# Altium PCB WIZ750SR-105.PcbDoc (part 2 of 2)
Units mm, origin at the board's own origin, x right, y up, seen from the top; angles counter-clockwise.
Board outline 62 x 40 mm, 4 copper layers (Top Layer, Signal Layer 1, Internal Plane 1, Bottom Layer), stack 0.844 mm thick; 87 components, 85 nets, 410 pads, 285 vias.
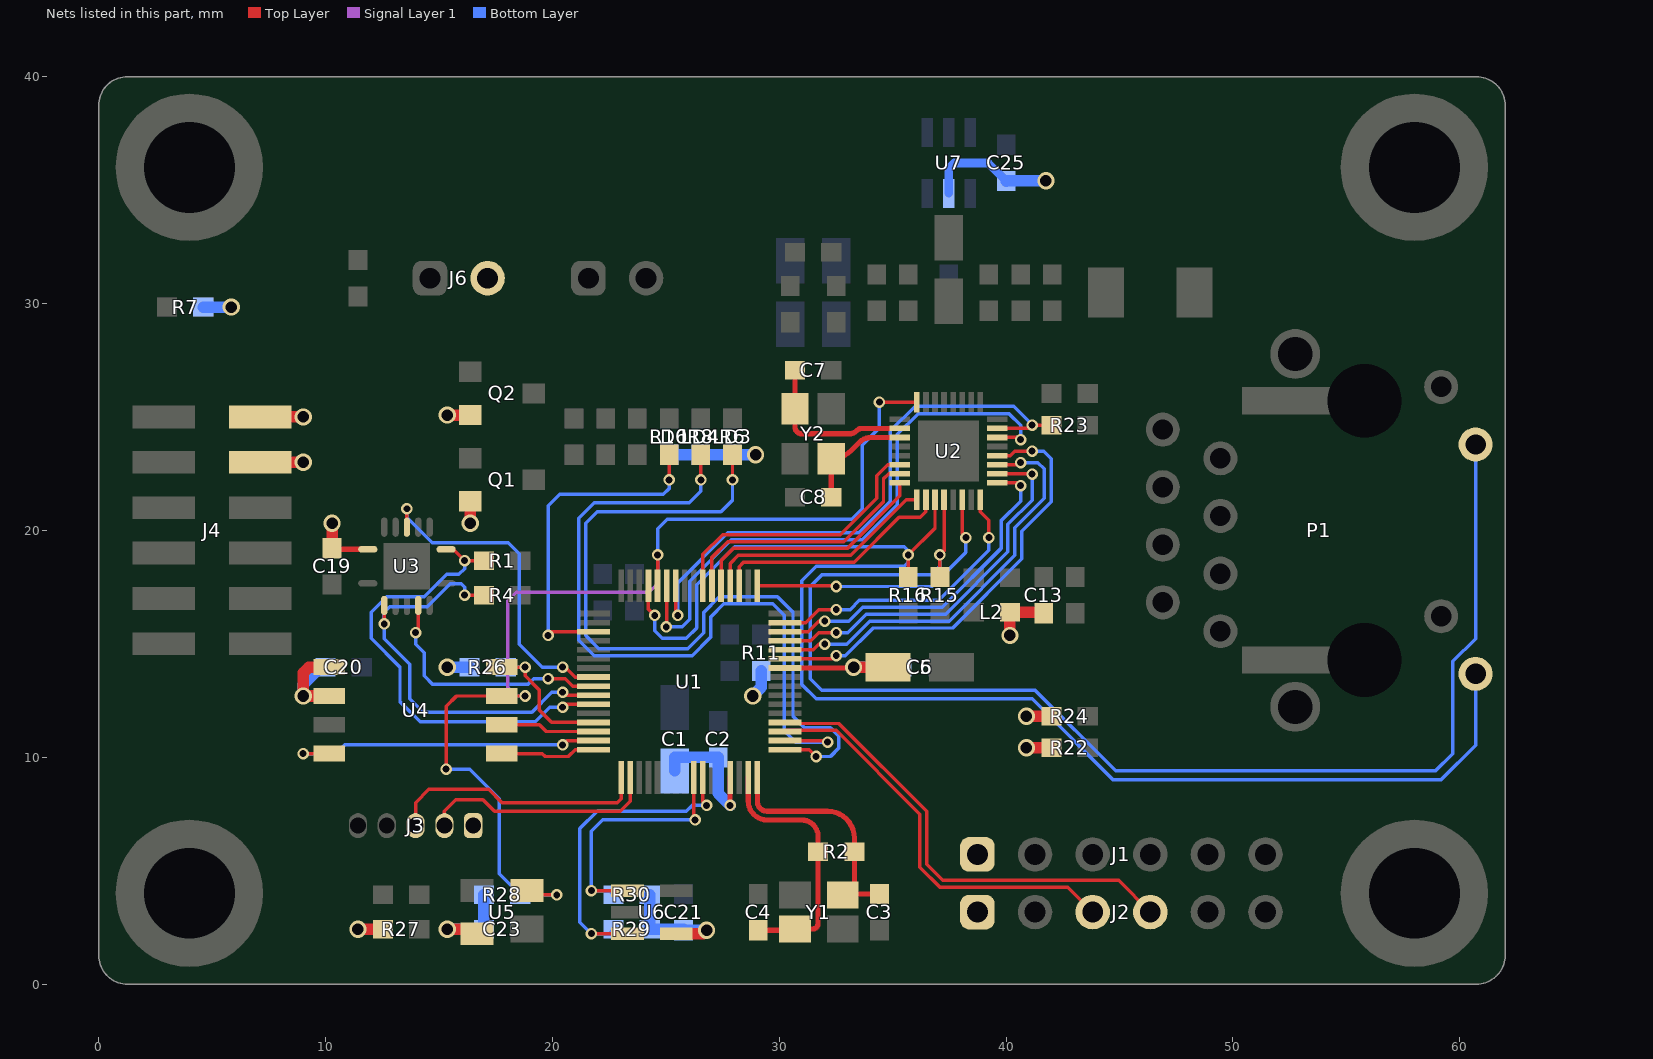
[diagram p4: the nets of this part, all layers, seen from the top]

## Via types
v1: diameter 0.508, hole 0.305, Top Layer to Bottom Layer, tented both sides, 164 vias
v2: diameter 0.762, hole 0.508, Top Layer to Bottom Layer, tented both sides, 119 vias
v3: diameter 0.508, hole 0.305, Top Layer to Bottom Layer, 1 vias
v4: diameter 0.508, hole 0.305, Top Layer to Bottom Layer, tented top, 1 vias

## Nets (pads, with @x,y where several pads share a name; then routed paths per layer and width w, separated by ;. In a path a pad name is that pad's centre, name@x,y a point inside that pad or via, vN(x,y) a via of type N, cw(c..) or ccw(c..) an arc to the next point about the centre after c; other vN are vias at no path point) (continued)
PB_07: U1.17 U2.14 | length 12.8
  Top Layer w0.152: U1.17@29.035,18.138 U1.17@29.035,17.56 32.478,17.56 v1(32.512,17.526) ; U2.14@38.065,21.345 38.065,19.847 v1(38.227,19.685)
  Bottom Layer w0.152: v1(32.512,17.526) 36.728,17.526 38.227,19.025 v1(38.227,19.685)
PB_09: U1.19 U2.10 | length 10.6
  Top Layer w0.152: U1.19@28.235,17.56 28.235,18.405 28.423,18.593 33.299,18.593 35.281,20.574 36.211,20.574 36.465,20.828 U2.10@36.465,21.345
PB_10: U1.20 U2.9 | length 10.4
  Top Layer w0.152: U1.20@27.835,17.56 27.835,18.539 28.194,18.898 33.147,18.898 35.594,21.345 U2.9@36.065,21.345
PB_11: U1.21 U2.8 | length 10.7
  Top Layer w0.152: U1.21@27.435,17.56 27.435,18.672 27.965,19.202 32.995,19.202 35.315,21.523 U2.8@35.315,22.095
PB_12: U1.22 U2.7 | length 11.6
  Top Layer w0.152: U1.22@27.035,17.56 27.035,18.805 27.737,19.507 32.842,19.507 34.595,21.26 34.595,22.27 34.82,22.495 U2.7@35.315,22.495
PB_13: U1.23 U2.6 | length 12.3
  Top Layer w0.152: U1.23@26.635,17.56 26.635,18.939 27.508,19.812 32.69,19.812 34.29,21.412 34.29,22.403 34.782,22.895 U2.6@35.315,22.895
PB_14: R23.1 U1.26 U2.23 | length 26.2
  Top Layer w0.152: U1.26@25.435,17.56 25.435,16.348 v1(25.527,16.256) ; U2.23@39.615,24.495 41.005,24.495 v1(41.148,24.638) R23.1@41.999,24.638
  Bottom Layer w0.152: v1(25.527,16.256) 25.527,17.678 27.737,19.888 33.503,19.888 34.9,21.285 34.9,24.384 35.992,25.476 40.331,25.476 41.148,24.659 v1(41.148,24.638)
PB_15: U1.27 U2.22 | length 26
  Top Layer w0.152: v1(25.019,15.748) 25.035,15.764 U1.27@25.035,17.56 ; U2.22@39.615,24.095 40.548,24.095 v1(40.64,24.003)
  Bottom Layer w0.152: v1(25.019,15.748) 25.73,15.748 26.06,16.078 26.06,17.755 27.889,19.583 33.655,19.583 35.204,21.133 35.204,24.232 36.119,25.146 40.129,25.146 40.64,24.635 v1(40.64,24.003)
PD_00: U1.11 U2.20 | length 19.8
  Top Layer w0.152: U1.11@30.26,14.335 32.369,14.335 v1(32.512,14.478) ; U2.20@39.615,23.295 40.186,23.295 40.386,23.495 v1(41.148,23.495)
  Bottom Layer w0.152: v1(32.512,14.478) 32.918,14.478 34.138,15.697 37.643,15.697 40.691,18.745 40.691,19.964 41.986,21.26 41.986,23.165 41.656,23.495 v1(41.148,23.495)
PD_01: U1.12 U2.19 | length 18.4
  Top Layer w0.152: U1.12@30.26,14.735 31.499,14.735 31.75,14.986 v1(32.004,14.986) ; U2.19@39.615,22.895 40.548,22.895 v1(40.64,22.987)
  Bottom Layer w0.152: v1(32.004,14.986) 32.969,14.986 33.985,16.002 37.49,16.002 40.386,18.898 40.386,20.117 41.681,21.412 41.681,22.708 41.402,22.987 v1(40.64,22.987)
PD_02: U1.13 U2.18 | length 16.9
  Top Layer w0.152: U1.13@30.26,15.135 31.391,15.135 31.75,15.494 v1(32.512,15.494) ; U2.18@39.615,22.495 41.132,22.495 v1(41.148,22.479)
  Bottom Layer w0.152: v1(32.512,15.494) 33.02,15.494 33.833,16.307 37.338,16.307 40.081,19.05 40.081,20.269 41.148,21.336 v1(41.148,22.479)
PD_03: U1.14 U2.17 | length 15.2
  Top Layer w0.152: U1.14@30.26,15.535 31.283,15.535 31.75,16.002 v1(32.004,16.002) ; U2.17@39.615,22.095 40.516,22.095 v1(40.64,21.971)
  Bottom Layer w0.152: v1(32.004,16.002) 33.071,16.002 33.68,16.612 37.186,16.612 39.776,19.202 39.776,20.422 40.64,21.285 v1(40.64,21.971)
PD_04: U1.15 U2.16 | length 12.7
  Top Layer w0.152: U1.15@30.26,15.935 31.175,15.935 31.75,16.51 v1(32.512,16.51) ; U2.16@38.865,21.345 38.865,20.825 39.243,20.447 v1(39.243,19.685)
  Bottom Layer w0.152: v1(32.512,16.51) 33.122,16.51 33.528,16.916 37.033,16.916 39.243,19.126 v1(39.243,19.685)
PHY_AD0: P1.L4 R16.2 U1.29 U2.11 | length 65.5
  Top Layer w0.152: U1.29@24.235,17.56 24.235,16.532 v1(24.511,16.256) ; R16.2@35.687,17.945 v1(35.687,18.923) 36.865,20.101 U2.11@36.865,21.345
  Bottom Layer w0.152: v1(24.511,16.256) 24.511,15.57 24.841,15.24 25.908,15.24 26.365,15.697 26.365,17.602 28.042,19.279 35.509,19.279 35.687,19.101 v1(35.687,18.923) 35.687,18.59 35.512,18.415 31.623,18.415 30.988,17.78 30.988,13.208 31.623,12.573 41.148,12.573 44.704,9.017 59.182,9.017 60.695,10.53 P1.L4@60.695,13.675
PHY_AD3: P1.L2 R15.2 U2.12 | length 58.5
  Top Layer w0.152: R15.2@37.084,17.945 v1(37.084,18.923) 37.265,19.104 U2.12@37.265,21.345
  Bottom Layer w0.152: v1(37.084,18.923) 37.084,18.415 36.703,18.034 31.877,18.034 31.369,17.526 31.369,13.462 31.877,12.954 41.275,12.954 44.831,9.398 58.928,9.398 59.69,10.16 59.69,14.224 60.695,15.229 P1.L2@60.695,23.785
RESETN: R28.1 U1.28 U2.32 U4.3 U5.2 | length 48.4
  Top Layer w0.152: v3(15.316,9.474) 15.316,12.243 15.773,12.7 U4.3@17.77,12.7 v1(18.796,12.7) ; U5.2@18.88,4.125 19.068,3.937 v1(20.193,3.937) ; U1.28@24.635,17.56 24.635,18.92 v1(24.638,18.923) ; v1(34.417,25.654) 34.417,25.645 U2.32@36.065,25.645
  Signal Layer 1 w0.152: v1(18.796,12.7) 18.415,12.7 18.034,13.081 18.034,16.891 18.415,17.272 24.257,17.272 24.638,17.653 v1(24.638,18.923)
  Bottom Layer w0.152: v3(15.316,9.474) 16.358,9.474 17.653,8.179 17.653,4.864 R28.1@18.58,3.937 v1(20.193,3.937) ; v1(24.638,18.923) 24.638,20.066 25.07,20.498 33.198,20.498 33.655,20.955 33.655,23.749 34.417,24.511 v1(34.417,25.654)
SCL1: R30.1 U1.57 U6.1 | length 11.9
  Top Layer w0.152: v1(21.717,4.125) U6.1@23.309,4.125 ; U1.57@26.235,9.11 26.235,7.293 v1(26.289,7.239)
  Bottom Layer w0.152: R30.1@22.695,3.937 22.507,4.125 v1(21.717,4.125) 21.717,6.731 22.225,7.239 v1(26.289,7.239)
SDA1: R29.1 U1.58 U6.3 | length 14.8
  Top Layer w0.152: v1(21.717,2.225) U6.3@23.309,2.225 ; U1.58@26.635,9.11 26.635,8.036 v1(26.797,7.874)
  Bottom Layer w0.152: R29.1@22.695,2.413 22.507,2.225 v1(21.717,2.225) 21.209,2.733 21.209,6.858 21.971,7.62 25.908,7.62 26.162,7.874 v1(26.797,7.874)
SPI_MISO1: U1.47 U4.8 | length 14.2
  Top Layer w0.152: v1(9.017,10.16) U4.8@10.17,10.16 ; v1(20.447,10.541) 20.641,10.735 U1.47@21.81,10.735
  Bottom Layer w0.152: v1(9.017,10.16) 10.465,10.16 10.846,10.541 v1(20.447,10.541)
SPI_MOSI1: U1.48 U4.1 | length 4.2
  Top Layer w0.152: U4.1@17.77,10.16 19.558,10.16 19.685,10.033 20.701,10.033 21.003,10.335 U1.48@21.81,10.335
SPI_SCLK1: U1.46 U4.2 | length 4.2
  Top Layer w0.152: U4.2@17.77,11.43 19.431,11.43 19.726,11.135 U1.46@21.81,11.135
SPI_SSEL1: R26.1 U1.45 U4.4 | length 6.6
  Top Layer w0.152: U4.4@17.77,13.97 v1(18.796,13.97) 18.796,13.589 19.431,12.954 19.431,12.065 19.961,11.535 U1.45@21.81,11.535
  Bottom Layer w0.152: R26.1@17.945,13.97 v1(18.796,13.97)
STATUS: LD6.2 U1.35 | length 14.9
  Top Layer w0.152: v1(19.812,15.367) 19.98,15.535 U1.35@21.81,15.535 ; v1(25.146,22.225) LD6.2@25.146,23.33
  Bottom Layer w0.152: v1(19.812,15.367) 19.812,21.082 20.32,21.59 24.892,21.59 25.146,21.844 v1(25.146,22.225)
STATUS_LED0: LD3.2 U1.1 | length 35.1
  Top Layer w0.152: v1(27.94,22.225) LD3.2@27.94,23.33 ; U1.1@30.26,10.335 31.321,10.335 v1(31.623,10.033)
  Bottom Layer w0.152: v1(27.94,22.225) 27.94,21.336 27.432,20.828 21.971,20.828 21.463,20.32 21.463,15.367 22.047,14.783 25.959,14.783 26.669,15.493 26.669,16.382 27.356,17.069 29.921,17.069 30.607,16.383 30.607,11.811 31.115,11.303 32.258,11.303 32.614,10.947 32.614,10.389 32.258,10.033 v1(31.623,10.033)
STATUS_LED1: LD4.2 U1.2 | length 33
  Top Layer w0.152: v1(26.543,22.225) LD4.2@26.543,23.33 ; U1.2@30.26,10.735 32.064,10.735 v1(32.131,10.668)
  Bottom Layer w0.152: v1(26.543,22.225) 26.543,21.717 26.035,21.209 21.844,21.209 21.161,20.526 21.161,15.161 21.844,14.478 26.162,14.478 26.971,15.287 26.971,16.176 27.559,16.764 29.718,16.764 30.226,16.256 30.226,11.176 30.734,10.668 v1(32.131,10.668)
SWCLK: J3.3 U1.49 | length 11.6
  Top Layer w0.152: J3.3@13.97,6.985 13.97,8.001 14.554,8.585 15.589,8.585 17.196,8.585 17.78,8.001 22.86,8.001 23.035,8.176 U1.49@23.035,9.11
SWDIO: J3.2 U1.50 | length 10.5
  Top Layer w0.152: J3.2@15.24,6.985 15.24,7.62 15.748,8.128 16.942,8.128 17.45,7.62 22.987,7.62 23.435,8.068 U1.50@23.435,9.11
U_CTS0: U1.40 U3.11 | length 14.7
  Top Layer w0.152: U3.11@13.589,20.14 v1(13.589,20.955) ; v1(20.447,13.97) 20.574,13.97 21.009,13.535 U1.40@21.81,13.535
  Bottom Layer w0.152: v1(13.589,20.955) 13.589,20.574 14.707,19.456 18.059,19.456 18.542,18.974 18.542,14.986 19.558,13.97 v1(20.447,13.97)
U_RTS0: U1.41 U3.5 | length 11.2
  Top Layer w0.152: v1(13.97,15.494) 14.089,15.613 U3.5@14.089,16.69 ; v1(19.812,13.462) 20.574,13.462 20.901,13.135 U1.41@21.81,13.135
  Bottom Layer w0.152: v1(13.97,15.494) 13.97,14.986 14.351,14.605 14.351,13.589 14.732,13.208 18.923,13.208 19.177,13.462 v1(19.812,13.462)
U_RXD0: R1.2 U1.43 U3.8 | length 20.8
  Top Layer w0.152: U3.8@15.314,19.165 15.633,19.165 v1(16.129,18.669) R1.2@16.98,18.669 ; v1(20.447,12.205) 20.577,12.335 U1.43@21.81,12.335
  Bottom Layer w0.152: v1(16.129,18.669) 16.129,18.313 15.875,18.059 15.342,18.059 14.352,17.069 12.701,17.069 12.014,16.382 12.014,15.24 13.284,13.97 13.284,12.447 13.373,12.357 14.174,11.557 19.24,11.557 19.888,12.205 v1(20.447,12.205)
U_RXD2: J2.4 U1.4 | length 20.9
  Top Layer w0.152: U1.4@30.26,11.535 30.308,11.487 32.632,11.487 36.5,7.619 36.5,5.283 37.211,4.572 44.958,4.572 J2.4@46.355,3.175
U_TXD0: R4.2 U1.42 U3.2 | length 19.2
  Top Layer w0.152: v1(12.589,15.875) U3.2@12.589,16.69 ; v1(16.129,17.145) R4.2@16.98,17.145 ; v1(20.447,12.865) 20.577,12.735 U1.42@21.81,12.735
  Bottom Layer w0.152: v1(16.129,17.145) 16.129,17.501 15.977,17.653 15.494,17.653 14.478,16.637 12.827,16.637 12.573,16.383 12.573,15.891 v1(12.589,15.875) 12.589,15.224 13.716,14.097 13.716,12.573 14.3,11.989 19.101,11.989 19.977,12.865 v1(20.447,12.865)
U_TXD2: J2.3 U1.3 | length 18.3
  Top Layer w0.152: U1.3@30.26,11.135 30.308,11.183 32.505,11.183 36.195,7.493 36.195,5.157 37.085,4.267 42.723,4.267 J2.3@43.815,3.175
VCC_3.3V: C1.1 C2.2 C5.1 C6.2 C13.2 C19.1 C20.1 C21.2 C23.2 C25.1 J1.1 J2.1 J3.1 J4.2 J4.4 J6.2 L2.1 Q1.2 Q2.2 R6.2 R7.1 R8.2 R10.2 R11.2 R22.1 R24.1 R26.2 R27.2 R28.2 R29.2 R30.2 U1.10 U1.61 U3.14 U4.5 U4.6 U5.4 U6.4 U7.5 | length 55.2
  Top Layer w0.229: v1(27.835,7.874) U1.61@27.835,9.11 ; U1.10@30.26,13.935 33.239,13.935 v2(33.274,13.97)
  Top Layer w0.254: C19.1@10.287,19.215 C19.1@10.337,19.165 ; C19.1@10.464,19.165 U3.14@11.864,19.165
  Top Layer w0.508: J4.4@7.13,23 v2(9.017,23) ; J4.2@7.13,25 v2(9.017,25) ; U4.6@10.17,12.7 v2(9.017,12.7) 9.017,13.716 9.271,13.97 U4.5@10.17,13.97 ; C19.1@10.287,19.215 v2(10.287,20.32) ; v2(11.43,2.413) R27.2@12.535,2.413 ; v2(15.367,2.413) 16.492,2.413 U5.4@16.68,2.225 ; v2(15.367,25.085) Q2.2@16.38,25.085 ; Q1.2@16.38,21.275 16.383,21.272 v2(16.383,20.32) ; U6.4@25.459,2.225 26.647,2.225 v2(26.797,2.375) ; v2(33.274,13.97) C5.1@34.795,13.97 ; v2(40.17,15.367) L2.1@40.17,16.383 41.618,16.383 C13.2@41.656,16.345 ; v2(40.894,10.414) R22.1@41.999,10.414 ; v2(40.894,11.811) R24.1@41.999,11.811
  Bottom Layer w0.381: U7.5@37.465,34.855 37.465,35.941 37.719,36.195 39.205,36.195 C25.1@40.005,35.395
  Bottom Layer w0.508: R7.1@4.61,29.845 v2(5.842,29.845) ; v2(9.017,12.7) 9.017,13.208 9.779,13.97 C20.1@9.995,13.97 ; v2(15.367,2.413) C23.2@16.98,2.413 R28.2@16.98,3.937 ; v2(15.367,13.97) R26.2@16.345,13.97 ; R30.2@24.295,3.937 R29.2@24.295,2.413 25.781,2.413 C21.2@25.781,2.375 v2(26.797,2.375) ; R10.2@25.146,23.33 R8.2@26.543,23.33 R6.2@27.94,23.33 v2(28.956,23.33) ; C1.1@25.4,9.395 25.4,9.995 C2.2@27.305,9.995 27.305,8.404 v1(27.835,7.874) ; v2(28.829,12.7) 29.21,13.081 R11.2@29.21,13.805 ; v2(33.274,13.97) C6.2@35.395,13.97 ; C25.1@40.005,35.395 40.018,35.408 v2(41.758,35.408)
XIN: C4.2 R2.2 U1.63 Y1.3 | length 11.6
  Top Layer w0.229: U1.63@28.635,9.11 28.635,8.063 ccw(c29.464,8.063) 29.464,7.234 30.988,7.234 cw(c30.988,6.51) 31.712,6.51 R2.2@31.712,5.842 31.712,2.667 cw(c31.47,2.667) 31.47,2.425 Y1.3@30.7,2.425 cw(c30.65,2.425) 30.65,2.375 C4.2@29.083,2.375
XOUT: C3.2 R2.1 U1.64 Y1.1 | length 10.6
  Top Layer w0.229: U1.64@29.035,9.11 29.035,8.049 ccw(c29.464,8.049) 29.464,7.62 32.131,7.62 cw(c32.131,6.439) 33.312,6.439 R2.1@33.312,5.842 33.312,4.437 cw(c32.85,4.437) 32.85,3.975 C3.2@34.417,3.975
XTAL1: C7.2 U2.2 Y2.1 | length 7.4
  Top Layer w0.229: C7.2@30.696,27.051 Y2.1@30.696,25.357 30.696,24.549 ccw(c30.988,24.549) 30.988,24.257 33.094,24.257 ccw(c33.094,24.691) 33.401,24.384 cw(c33.669,24.116) 33.669,24.495 U2.2@35.315,24.495
XTAL2: C8.2 U2.3 Y2.3 | length 5
  Top Layer w0.229: C8.2@32.296,21.463 Y2.3@32.296,23.157 ccw(c32.296,24.395) 33.172,23.52 33.528,23.876 cw(c34.057,23.347) 34.057,24.095 U2.3@35.315,24.095
pads on no net: J4.10 M1.1 M2.1 M4.1 P1. P1.R4 P1.R5 P1.R6 U1.30 U1.31 U1.33 U1.38 U1.44 U1.51 U1.52 U1.53 U1.54 U1.55 U1.56 U1.59 U1.60 U2.1 U2.21
copper on no net:
  other v2: 4,1.4 58,1.4 2.162,2.162 5.838,2.162 56.162,2.162 59.838,2.162 1.4,4 6.6,4 55.4,4 60.6,4 2.162,5.838 5.838,5.838 56.162,5.838 59.838,5.838 4,6.6 58,6.6 4,33.4 2.162,34.162 5.838,34.162 1.4,36 6.6,36 2.162,37.838 5.838,37.838 4,38.6

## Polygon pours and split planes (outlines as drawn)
CH_GND on Top Layer "Top Layer-NET" (solid, remove dead copper, pour order 14): 61.341,39.116 61.341,28.321 61.087,28.067 54.483,28.067 53.34,26.924 52.197,26.924 51.054,28.067 47.752,28.067 47.498,28.321 47.498,39.116 47.752,39.37 61.087,39.37
GND on Top Layer "Top Layer-GND" (solid, remove dead copper, pour order 18): 42.545,28.956 42.545,26.797 42.291,26.543 42.037,26.543 33.909,26.543 33.655,26.797 33.655,27.178 33.655,28.956
GND on Top Layer "Top Layer-GND" (solid, remove dead copper, pour order 20): 45.212,36.195 45.212,9.144 45.466,8.89 45.72,8.89 52.832,8.89 53.086,8.636 53.086,8.382 53.086,0.889 52.832,0.635 52.451,0.635 9.144,0.635 8.89,0.889 8.89,1.016 8.89,8.636 8.636,8.89 7.493,8.89 0.889,8.89 0.635,9.144 0.635,9.271 0.635,30.861 0.889,31.115 1.27,31.115 8.636,31.115 8.89,31.369 8.89,31.496 8.89,39.116 9.144,39.37 9.398,39.37 44.958,39.37 45.212,39.116
GND on Bottom Layer "Top Layer-GND" (solid, remove dead copper, pour order 8): 45.212,36.195 45.212,9.144 45.466,8.89 45.72,8.89 52.832,8.89 53.086,8.636 53.086,8.382 53.086,0.889 52.832,0.635 52.451,0.635 9.144,0.635 8.89,0.889 8.89,1.016 8.89,8.636 8.636,8.89 7.493,8.89 0.889,8.89 0.635,9.144 0.635,9.271 0.635,30.861 0.889,31.115 1.27,31.115 8.636,31.115 8.89,31.369 8.89,31.496 8.89,39.116 9.144,39.37 9.398,39.37 44.958,39.37 45.212,39.116
CH_GND on Bottom Layer "Top Layer-NET" (solid, remove dead copper, pour order 12): 61.341,35.306 61.341,28.321 61.087,28.067 54.737,28.067 54.483,27.813 54.483,27.686 54.483,11.176 54.229,10.922 51.308,10.922 51.054,11.176 51.054,27.813 50.8,28.067 47.752,28.067 47.498,28.321 47.498,39.116 47.752,39.37 61.087,39.37 61.341,39.116
GND on Signal Layer 1 "Top Layer-GND" (solid, remove dead copper, pour order 6): 45.212,36.195 45.212,9.144 45.466,8.89 45.72,8.89 52.832,8.89 53.086,8.636 53.086,8.382 53.086,0.889 52.832,0.635 52.451,0.635 9.144,0.635 8.89,0.889 8.89,1.016 8.89,8.636 8.636,8.89 7.493,8.89 0.889,8.89 0.635,9.144 0.635,9.271 0.635,30.861 0.889,31.115 1.27,31.115 8.636,31.115 8.89,31.369 8.89,31.496 8.89,39.116 9.144,39.37 9.398,39.37 44.958,39.37 45.212,39.116
IP_3.3V on Internal Plane 1 (split plane): 37.146,30.48 37.152,30.418 37.17,30.358 37.2,30.303 37.239,30.254 37.288,30.215 37.343,30.185 37.403,30.167 37.465,30.161 45.274,30.161 45.274,17.464 39.37,17.464 39.308,17.458 39.248,17.44 39.193,17.41 39.144,17.371 39.105,17.322 39.075,17.267 39.057,17.207 39.051,17.145 39.051,14.924 35.244,14.924 35.244,27.94 35.238,28.002 35.22,28.062 35.19,28.117 35.151,28.166 35.102,28.205 35.047,28.235 34.987,28.253 34.925,28.259 28.513,28.259 28.513,34.352 37.146,34.352
VCC_3.3V on Internal Plane 1 (split plane): 45.339,30.799 37.784,30.799 37.784,34.671 37.778,34.733 37.76,34.793 37.73,34.848 37.691,34.897 37.642,34.936 37.587,34.966 37.527,34.984 37.465,34.99 28.194,34.99 28.132,34.984 28.072,34.966 28.017,34.936 27.968,34.897 27.929,34.848 27.899,34.793 27.881,34.733 27.875,34.671 27.875,27.94 27.881,27.878 27.899,27.818 27.929,27.763 27.968,27.714 28.017,27.675 28.072,27.645 28.132,27.627 28.194,27.621 34.606,27.621 34.606,14.605 34.612,14.543 34.63,14.483 34.66,14.428 34.699,14.379 34.748,14.34 34.803,14.31 34.863,14.292 34.925,14.286 39.37,14.286 39.432,14.292 39.492,14.31 39.547,14.34 39.596,14.379 39.635,14.428 39.665,14.483 39.683,14.543 39.689,14.605 39.689,16.826 45.339,16.826 45.339,8.89 53.086,8.89 53.086,0.51 8.89,0.51 8.89,8.89 0.51,8.89 0.51,31.11 8.89,31.11 8.89,39.49 45.339,39.49

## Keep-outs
Keep-Out Layer:
  the board outline again, w0.127
  text ".Layer_Name" at 9.398,44.45 h1.52

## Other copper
Top Layer:
  pour cut-out: 10.211,22.352 9.627,22.936 9.627,22.352
  pour cut-out: 14.021,14.148 14.376,13.792 14.376,9.119 13.233,7.976 11.862,7.976 11.862,7.62 13.811,7.62 13.811,7.893 14.681,8.763 14.681,14.148
  pour cut-out: 15.723,5.006 14.374,5.006 13.607,5.773 13.607,5.992 13.658,6.043 16.71,6.043 16.71,6.123 13.563,6.123 13.487,6.123 13.487,6.047 13.487,5.817 13.487,5.69 13.564,5.69 14.249,5.004 14.249,4.877 15.723,4.877
  pour cut-out: 1.168,26.035 0.533,26.67 0.533,26.035
  pour cut-out: 15.138,22.352 15.545,22.758 15.545,22.352
  pour cut-out: 5.842,15.748 5.842,25.527 4.191,25.527 4.191,15.748
  pour cut-out: 1.524,15.494 0.508,15.494 0.508,16.129 1.524,16.129
  pour cut-out: 8.763,26.035 8.763,25.527 0.508,25.527 0.508,26.035
  pour cut-out: 15.621,22.352 8.636,22.352 8.636,19.685 15.621,19.685
  pour cut-out: 20.577,16.968 19.431,16.968 19.431,16.383 20.577,16.383
  pour cut-out: 24.892,20.32 26.924,20.32 26.924,19.431 24.892,19.431
  pour cut-out: 22.225,19.692 24.257,19.692 24.257,18.669 22.225,18.669
  pour cut-out: 11.176,14.224 11.811,14.224 11.176,13.589
  pour cut-out: 18.978,9.302 20.986,9.302 21.463,9.779 18.923,9.779
  pour cut-out: 40.005,18.542 40.005,20.828 40.259,21.082 41.783,21.082 42.037,21.336 42.037,23.724 42.189,23.876 39.37,23.876 39.243,23.749 39.243,18.542
  pour cut-out: 44.323,24.028 44.475,23.876 45.187,23.876 45.339,24.028 45.339,22.86 44.323,22.86
  pour cut-out: 41.402,9.855 40.488,9.855 40.488,9.703 40.462,9.677 37.719,9.677 37.465,9.677 37.465,9.423 37.516,9.373 41.402,9.373
  pour cut-out: 44.323,12.602 45.139,12.602 45.39,12.852 45.39,12.421 44.323,12.421
  pour cut-out: 43.809,18.771 45.146,18.771 45.369,18.994 45.369,18.66 45.35,18.671 43.809,18.671
  pour cut-out: 40.919,18.771 40.071,18.771 39.929,18.913 39.929,18.694 40.386,18.694 40.919,18.694
  pour cut-out: 42.828,28.905 42.828,26.971 43.18,26.619 42.469,26.619 42.469,28.854 42.418,28.905
  pour cut-out: 45.06,31.902 45.314,32.156 45.314,31.902
  pour cut-out: 43.002,23.698 42.824,23.876 43.002,23.876
  pour cut-out: 32.766,28.27 32.766,27.889 32.69,27.813 32.969,27.813 32.969,28.346 32.969,28.422 32.614,28.422
  pour cut-out: 29.689,33.532 30.295,34.163 32.639,34.163 33.122,33.68 33.122,29.566 31.75,29.566 31.674,29.642 31.318,29.642 31.242,29.566 29.689,29.566
  pour cut-out: 29.885,22.034 29.844,22.075 28.605,22.075 28.374,21.844 28.374,22.19 29.885,22.19
  pour cut-out: 28.597,20.449 28.597,22.301 28.169,22.301 28.169,20.449
  pour cut-out: 22.682,21.844 24.333,21.844 24.333,21.285 24.333,21.107 22.682,21.107
  pour cut-out: 26.817,6.98 27.026,7.188 28.473,7.188 28.519,7.142 28.52,7.315 26.848,7.315
  pour cut-out: 23.8,7.823 24.003,8.026 23.8,8.026
  pour cut-out: 25.806,7.899 25.679,8.026 25.806,8.026
  pour cut-out: 15.579,1.344 15.191,1.344 14.884,1.651 15.57,1.651
  pour cut-out: 17.781,1.344 18.526,1.344 18.626,1.444 17.781,1.444
  pour cut-out: 12.877,4.674 12.04,4.674 12.243,4.877 12.243,5.639 11.787,6.095 11.684,6.095 11.684,6.172 12.877,6.172
  pour cut-out: 7.874,8.413 8.89,8.413 8.89,8.738 9.627,9.474 9.627,9.957 8.414,9.957 8.414,9.379 7.874,8.839
  pour cut-out: 8.37,13.695 8.37,13.949 8.406,13.949 8.406,13.695
  pour cut-out: 18.237,8.255 17.958,8.534 17.958,9.322 18.161,9.525 17.78,9.525 17.78,8.255
  pour cut-out: 22.25,8.357 22.682,8.788 22.682,9.474 22.25,9.906 22.784,9.906 22.784,8.357
  pour cut-out: 19.981,5.006 20.701,4.286 19.981,4.286
  pour cut-out: 32.207,9.881 32.309,9.982 33.122,9.982 33.122,10.084 32.207,10.058
  pour cut-out: 35.208,4.801 36.245,4.801 36.525,4.521 35.509,4.521 35.204,4.216
  pour cut-out: 45.314,17.272 45.009,17.577 45.314,17.577
  pour cut-out: 43.764,17.297 44.044,17.577 43.764,17.577
  pour cut-out: 28.731,24.492 28.864,24.359 29.591,24.359 29.743,24.511 29.743,24.282 28.651,24.282 28.651,24.562
  pour cut-out: 33.499,32.106 33.299,32.106 33.122,32.283 33.121,31.674 33.503,31.674
  pour cut-out: 20.061,26.866 18.211,26.866 17.261,27.816 18.133,27.816 19.111,27.816
  pour cut-out: 22.098,29.995 23.876,29.996 23.876,30.3 22.098,30.3
  pour cut-out: 22.555,31.979 22.657,31.877 23.266,31.877 23.317,31.928 23.317,31.801 22.555,31.801
  pour cut-out: 13.627,30.302 13.195,30.734 13.627,30.734
  pour cut-out: 12.192,30.836 12.294,30.937 12.725,30.937 12.852,30.937 12.852,30.836 12.268,30.836 12.192,30.759
  pour cut-out: 29.715,26.438 29.715,27.687 29.87,27.842 29.87,26.438
  pour cut-out: 20.061,26.866 28.1,26.866 28.727,26.238 28.727,24.561 20.061,24.561
  pour cut-out: 33.731,31.979 33.884,32.131 33.884,32.41 34.265,32.791 35.789,32.791 36.119,32.461 36.119,32.156 36.297,31.979
  pour cut-out: -0.8,36 ccw(c4,36) 4,31.2 ccw(c4,36) 8.8,36 ccw(c4,36) 4,40.8 ccw(c4,36)
  pour cut-out: -0.8,4 ccw(c4,4) 4,-0.8 ccw(c4,4) 8.8,4 ccw(c4,4) 4,8.8 ccw(c4,4)
  pour cut-out: 53.2,4 ccw(c58,4) 58,-0.8 ccw(c58,4) 62.8,4 ccw(c58,4) 58,8.8 ccw(c58,4)
  text ".Layer_Name" at 9.398,44.45 h1.52
Signal Layer 1:
  pour cut-out: -0.8,36 ccw(c4,36) 4,31.2 ccw(c4,36) 8.8,36 ccw(c4,36) 4,40.8 ccw(c4,36)
  pour cut-out: -0.8,4 ccw(c4,4) 4,-0.8 ccw(c4,4) 8.8,4 ccw(c4,4) 4,8.8 ccw(c4,4)
  pour cut-out: 53.2,4 ccw(c58,4) 58,-0.8 ccw(c58,4) 62.8,4 ccw(c58,4) 58,8.8 ccw(c58,4)
  text ".Layer_Name" at 9.398,44.45 h1.52
Bottom Layer:
  pour cut-out: 20.447,9.906 21.158,9.195 21.158,8.052 21.387,8.052 21.692,8.357 21.692,10.109 20.447,10.109
  pour cut-out: 16.561,9.5 17.501,8.56 17.501,9.627 18.11,10.236 16.561,10.236
  pour cut-out: 13.106,5.842 13.36,6.096 13.106,6.096
  pour cut-out: 17.221,5.766 16.944,6.043 17.221,6.043
  pour cut-out: 17.145,6.043 13.03,6.043 13.03,6.248 17.145,6.248
  pour cut-out: 11.76,6.172 12.344,6.172 12.344,5.588
  pour cut-out: 12.446,13.919 12.903,13.462 12.903,13.919
  pour cut-out: 19.939,11.659 20.193,11.659 20.193,11.735 19.939,11.735
  pour cut-out: 13.564,10.541 13.259,10.541 13.259,10.947 13.462,11.151 13.462,11.608 13.31,11.76 19.304,11.76 19.304,10.541
  pour cut-out: 12.065,1.778 12.065,0.508 12.573,0.508 12.573,1.778
  pour cut-out: 2.836,9.906 2.836,9.313 2.413,8.89 3.429,8.89 3.429,9.906
  pour cut-out: 8.636,31.115 6.731,29.21 6.477,28.956 0.508,28.956 0.508,31.115
  pour cut-out: 35.8,21.516 35.8,19.318 35.814,19.304 35.789,19.279 34.671,19.279 34.671,21.463
  pour cut-out: 39.751,24.638 40.259,24.638 40.259,21.082 39.751,21.082
  pour cut-out: 19.812,25.654 28.629,25.654 28.858,25.883 28.858,26.641 28.575,26.924 19.812,26.924
  pour cut-out: 49.174,1.676 49.174,0.533 49.497,0.533 49.361,0.707 49.361,1.676
  pour cut-out: 53.213,8.255 53.213,8.661 52.807,8.661
  pour cut-out: 34.875,25.866 34.875,25.942 36.044,25.942 36.095,25.993 36.095,26.78 36.374,26.78 36.374,25.866
  pour cut-out: 35.799,19.848 35.944,19.703 37.541,19.703 37.646,19.808 37.646,19.516 37.593,19.463 35.799,19.463
  pour cut-out: 42.422,19.453 42.215,19.66 41.351,19.66 40.975,19.284 40.976,19.66 42.422,21.106
  pour cut-out: 26.797,6.96 27.076,7.239 27.813,7.239 27.94,7.366 26.797,7.366
  pour cut-out: 22.479,4.648 22.123,5.004 22.123,4.648
  pour cut-out: 19.406,4.728 20.247,4.728 20.418,4.899 20.418,4.47 20.32,4.47 19.406,4.47
  pour cut-out: 16.154,4.728 15.977,4.547 15.977,2.972 16.408,2.972 16.408,4.728
  pour cut-out: 8.89,8.636 9.296,9.042 8.89,9.042
  pour cut-out: 37.541,1.753 37.744,1.956 37.744,2.337 37.744,2.515 37.922,2.515 37.922,1.753
  pour cut-out: 29.474,33.261 30.427,34.214 32.565,34.214 33.518,33.261
  pour cut-out: 17.983,30.582 18.339,30.226 20.244,30.226 20.574,30.556 20.574,30.582 20.574,29.972 17.983,29.972
  pour cut-out: 21.607,29.214 22.559,30.166 23.607,30.166 23.607,30.376 23.58,30.404 21.607,30.404
  pour cut-out: 20.117,26.848 19.71,27.254 19.71,26.848
  pour cut-out: 22.555,31.979 22.657,31.877 23.266,31.877 23.317,31.928 23.317,31.801 22.555,31.801
  pour cut-out: 33.08,10.798 34.544,12.263 34.544,12.268 33.071,12.268
  pour cut-out: 29.261,12.141 29.972,11.43 29.972,12.141
  pour cut-out: 27.559,12.421 27.559,12.776 27.254,13.081 27.813,13.081 27.852,13.042 27.852,12.421
  pour cut-out: 27.022,14.059 26.352,14.059 26.213,14.199 27.026,14.199
  pour cut-out: 23.495,11.836 23.673,11.659 24.308,11.659 24.486,11.836 24.486,11.227 23.495,11.227
  pour cut-out: 28.096,9.169 28.096,8.411 28.042,8.357 27.952,8.446 27.952,9.169
  pour cut-out: 44.755,15.138 45.288,14.605 45.288,15.138
  pour cut-out: 43.79,30.963 44.628,30.963 45.39,31.725 45.39,30.734 43.815,30.734 43.79,30.759
  pour cut-out: 29.489,20.828 29.108,21.209 29.108,22.479 29.388,22.758 28.829,22.758 28.829,21.793 28.829,20.828
  pour cut-out: 39.751,37.821 39.05,38.522 39.05,37.836 39.065,37.821
  pour cut-out: 40.796,34.569 41.021,34.794 41.021,34.798 40.792,34.798
  pour cut-out: -0.8,36 ccw(c4,36) 4,31.2 ccw(c4,36) 8.8,36 ccw(c4,36) 4,40.8 ccw(c4,36)
  pour cut-out: -0.8,4 ccw(c4,4) 4,-0.8 ccw(c4,4) 8.8,4 ccw(c4,4) 4,8.8 ccw(c4,4)
  pour cut-out: 53.2,4 ccw(c58,4) 58,-0.8 ccw(c58,4) 62.8,4 ccw(c58,4) 58,8.8 ccw(c58,4)
  text ".Layer_Name" at 9.398,44.45 h1.52
Internal Plane 1 (plane layer: these items are gaps in the copper):
  region: 0,40 0,31.11 8.89,31.11 8.89,40
  rectangle: 0,0 8.89,8.89
  rectangle: 53.086,0 61.976,9.017
  rectangle: 45.649,14.239 50.729,25.669
  rectangle: 30.099,22.479 32.893,26.035
  rectangle: 29.972,1.778 33.528,4.572
  region: 45.339,40 61.849,40.005 61.849,8.89 45.339,8.89
  lines w0.635: 28.194,27.94 34.925,27.94 34.925,14.605 39.37,14.605 39.37,17.145 45.593,17.145 45.593,30.48 37.465,30.48 37.465,34.671 28.194,34.671 28.194,27.94
  text ".Layer_Name" at 9.398,44.45 h1.52
  text "VCC_3.3V" at 9.144,38.354 h0.76
  text "IP_3.3V" at 41.275,29.083 h0.76

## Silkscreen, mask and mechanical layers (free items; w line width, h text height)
Top Overlay:
  rectangle: 7.62,33.02 33.62,40.02
  text ".Layer_Name" at 9.398,44.482 h1.52
  text "WIZ750SR-105 V1.0" at 42.393,34.417 h1.52
  text "BOOT" at 15.748,28.702 h0.76
  text "APP_BOOT" at 20.193,28.702 h0.76
  text "Power LED" at 1.27,28.067 h0.76
  text "TX" at 21.336,25.781 h0.76 r90
  text "RX" at 22.733,25.781 h0.76 r90
  text "COL" at 25.527,25.781 h0.76 r90
Bottom Overlay:
  lines w0.2: 11.536,36.981 22.686,36.981 ; 13.161,34.441 22.686,34.441 ; 13.288,35.711 22.686,35.711
  text ".Layer_Name" at 9.398,44.45 h1.52
  text "WIZ750SR-105" at 22.686,37.235 h1.2
  text "http://wizwiki.net" at 22.686,36.092 h1
  text "Designed by WIZnet" at 22.686,34.822 h1
  text "RSTn" at 4.122,24.638 h0.76
  text "3.3V" at 8.382,24.638 h0.76
  text "RX" at 4.122,22.638 h0.76
  text "3.3V" at 8.382,22.638 h0.76
  text "CTS" at 4.122,20.638 h0.76
  text "FAC" at 8.382,20.638 h0.76
  text "TX" at 4.122,18.638 h0.76
  text "TRIG" at 8.382,18.638 h0.76
  text "RTS" at 4.122,16.638 h0.76
  text "NC" at 8.382,16.638 h0.76
  text "GND" at 4.122,14.638 h0.76
  text "GND" at 8.382,14.638 h0.76
  text "GND" at 11.811,11.049 h0.76 r90
  text "RESET" at 13.081,11.049 h0.76 r90
  text "SWCLK" at 14.351,11.049 h0.76 r90
  text "SWDIO" at 15.621,11.049 h0.76 r90
  text "VCC" at 16.891,11.049 h0.76 r90
  text "SWD" at 10.668,6.604 h0.76
  text "Expansion GPIO" at 37.338,5.334 h0.76
  text "ISP Port" at 37.338,2.794 h0.76
  text "3.3V" at 39.497,1.143 h0.76
  text "BOOT" at 42.672,1.143 h0.76
  text "TX" at 44.323,1.143 h0.76
  text "RX" at 46.863,1.143 h0.76
  text "RSTn" at 50.038,1.143 h0.76
  text "GND" at 52.451,1.143 h0.76
Top Paste:
  text ".Layer_Name" at 9.398,44.45 h1.52
Bottom Paste:
  text ".Layer_Name" at 9.398,44.45 h1.52
Top Solder:
  text ".Layer_Name" at 9.398,44.45 h1.52
Bottom Solder:
  text ".Layer_Name" at 9.398,44.45 h1.52
Drill Guide:
  text ".Layer_Name" at 9.398,44.45 h1.52
Mechanical 2:
  lines w0.127: 69.291,16.129 95.453,16.129 ; 69.291,18.923 95.453,18.923 ; 0,1.27 ccw(c1.27,1.27) 1.27,0 60.73,0 ccw(c60.73,1.27) 62,1.27 62,38.73 ccw(c60.73,38.73) 60.73,40 1.27,40 ccw(c1.27,38.73) 0,38.73 0,1.27 ; 67.945,4.775 ccw(c68.656,4.775) 68.656,4.064 95.834,4.064 ccw(c95.834,4.775) 96.545,4.775 96.545,24.003 ccw(c95.834,24.003) 95.834,24.714 68.656,24.714 ccw(c68.656,24.003) 67.945,24.003 67.945,4.775
  text "BOARD NAME : WIZ750SR-105" at 0,55.626 h1.52
  text "VERSION : V1.0" at 0,52.832 h1.52
  text "SIZE : 62mmX40mmX1.6T" at 0,50.038 h1.52
  text "GERBER DATE : 2017.12.27" at 0,47.244 h1.52
  text "LAYER :" at 0,44.45 h1.52
  text "Layer Stack Up Detail for:" at 69.418,22.606 h1.02
  text "WIZ750SR-105 V1.0.PcbDoc" at 69.291,20.193 h1.27
  text "Layer Name : 4L  1.6T" at 69.418,17.018 h1.02
  text "Top Layer" at 69.291,13.335 h1.52
  text "GND" at 69.291,10.541 h1.52
  text "POWER" at 69.291,7.874 h1.52
  text "Bottom Layer" at 69.291,5.334 h1.52
  text "KS Technology artwork" at 67.945,0 h5.08
Mechanical 3:
  drawing of 6954 lines, arcs and shapes, not listed
Drill Drawing:
  text ".Layer_Name" at 9.398,44.45 h1.52
  text ".Legend" at 69.977,27.432 h1.02

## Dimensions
1.27,0 to 1.27,40 on Mechanical 2
0,1.27 to 62,1.27 on Mechanical 2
